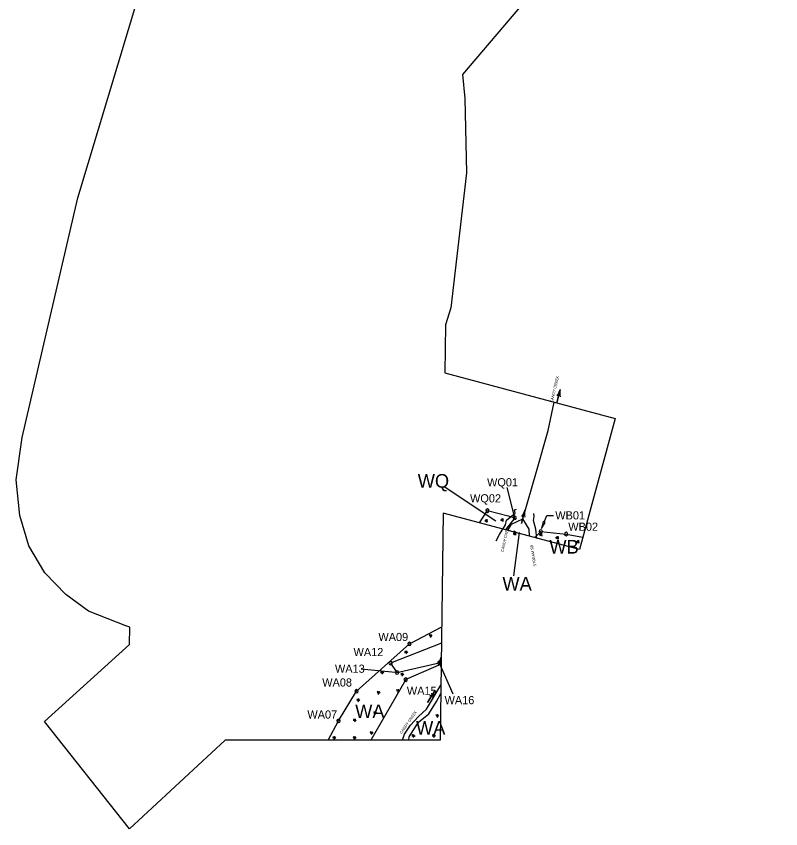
# Model space of a CAD drawing. Extents: x 1807340 to 1808565, y 913462 to 916154.
# Drawn here: x 1807340 to 1808463, y 913462 to 914655 of the extents above; entities that cross this region are included whole.
import ezdxf

# ---------------------------------------------------------------- set-up
doc = ezdxf.new("R2010")
doc.units = 0
for name, color, linetype in [('Default', 7, 'Continuous'), ('Exist Environmental Wetland Boundary', 7, 'Continuous'), ('Exist Hydro Jurisdictional Stream or Body of Water', 7, 'Continuous'), ('Exist Hydro River Flow Arrow CELL', 7, 'Continuous'), ('Exist Hydro Stream or Body of Water Text', 7, 'Continuous'), ('Old_Level_60', 7, 'Continuous'), ('Old_Level_61', 7, 'Continuous'), ('Prop PHM Study Limits Alternate 1', 7, 'Continuous')]:
    doc.layers.add(name, color=color, linetype=linetype)

# ---------------------------------------------------------------- blocks, each defined once
blk = doc.blocks.new('WetlandPoint')
at = {"layer": 'Default'}
for start, end in [(0, 180), (180, 0)]:
    blk.add_arc((0, 0), 0.782, start, end, dxfattribs=at)

msp = doc.modelspace()

# ---------------------------------------------------------------- linework, layer by layer
at = {"layer": 'Exist Environmental Wetland Boundary'}
for points in [[(1808020.3, 913911.2), (1808031.7, 913929.3), (1808062, 913921.8), (1808071.9, 913918.8), (1808058.3, 913901.1)], [(1808031.7, 913912.5), (1808031.6, 913914.6), (1808027.7, 913914.4), (1808031.6, 913914.6), (1808031.5, 913916.7)], [(1808055.1, 913913.6), (1808055, 913915.8), (1808051, 913915.5), (1808055, 913915.8), (1808054.9, 913917.9)], [(1808055.1, 913913.6), (1808055, 913915.8), (1808051, 913915.5), (1808055, 913915.8), (1808054.9, 913917.9)], [(1808074.5, 913896.8), (1808070.6, 913899.2), (1808070.5, 913897.9)], [(1808073.4, 913893.1), (1808073.3, 913895.3), (1808069.4, 913895.1), (1808073.3, 913895.3), (1808073.2, 913897.4)], [(1808101.2, 913889.7), (1808110, 913898.8), (1808147.3, 913895), (1808171.8, 913890.2)], [(1808112, 913892), (1808111.8, 913894.2), (1808107.9, 913894), (1808111.8, 913894.2), (1808111.7, 913896.3)], [(1808112, 913892), (1808111.8, 913894.2), (1808107.9, 913894), (1808111.8, 913894.2), (1808111.7, 913896.3)], [(1808136, 913887.5), (1808135.9, 913889.7), (1808131.9, 913889.4), (1808135.9, 913889.7), (1808135.8, 913891.8)], [(1808166.3, 913881.6), (1808166.2, 913883.8), (1808162.3, 913883.6), (1808166.2, 913883.8), (1808166.1, 913885.9)], [(1807797.7, 913592.3), (1807813, 913620.5), (1807839.6, 913664), (1807917.2, 913733.6), (1807964.6, 913758.5)], [(1807947.9, 913743.1), (1807949.3, 913744.7), (1807946.4, 913747.3), (1807949.3, 913744.7), (1807950.8, 913746.2)], [(1807964.3, 913734.5), (1807889.6, 913705.3), (1807898.9, 913691.6), (1807961, 913705.8), (1807964, 913714.1)], [(1807911.9, 913718.8), (1807913.3, 913720.3), (1807910.4, 913723), (1807913.3, 913720.3), (1807914.8, 913721.9)], [(1807963.9, 913704), (1807911.7, 913681.1), (1807860.6, 913592.3)], [(1807876.7, 913689), (1807878.1, 913690.6), (1807875.2, 913693.3), (1807878.1, 913690.6), (1807879.6, 913692.2)], [(1807906.2, 913686.1), (1807907.7, 913687.7), (1807904.8, 913690.4), (1807907.7, 913687.7), (1807909.1, 913689.3)], [(1807871.5, 913659.5), (1807872.9, 913661.1), (1807870, 913663.7), (1807872.9, 913661.1), (1807874.4, 913662.7)], [(1807899.9, 913662.3), (1807901.3, 913663.9), (1807898.4, 913666.6), (1807901.3, 913663.9), (1807902.8, 913665.5)], [(1807916.1, 913592.4), (1807916.8, 913596.9), (1807927.3, 913613.3), (1807930.7, 913618.6), (1807945.5, 913630.7), (1807956.8, 913649), (1807963.3, 913660.7)], [(1807841.5, 913648.5), (1807843, 913650.1), (1807840.1, 913652.7), (1807843, 913650.1), (1807844.4, 913651.6)], [(1807866.3, 913630), (1807867.7, 913631.5), (1807864.8, 913634.2), (1807867.7, 913631.5), (1807869.2, 913633.1)], [(1807957.7, 913625.6), (1807959.1, 913627.2), (1807956.2, 913629.9), (1807959.1, 913627.2), (1807960.6, 913628.8)], [(1807957.7, 913625.6), (1807959.1, 913627.2), (1807956.2, 913629.9), (1807959.1, 913627.2), (1807960.6, 913628.8)], [(1807836.3, 913618.9), (1807837.8, 913620.5), (1807834.9, 913623.2), (1807837.8, 913620.5), (1807839.2, 913622.1)], [(1807861.1, 913600.4), (1807862.5, 913602), (1807859.6, 913604.7), (1807862.5, 913602), (1807864, 913603.6)], [(1807806.2, 913593), (1807807.7, 913594.6), (1807804.8, 913597.3), (1807807.7, 913594.6), (1807809.1, 913596.2)], [(1807836.2, 913593.1), (1807837.7, 913594.7), (1807834.8, 913597.3), (1807837.7, 913594.7), (1807839.1, 913596.3)], [(1807922.5, 913596), (1807923.9, 913597.6), (1807921, 913600.3), (1807923.9, 913597.6), (1807925.4, 913599.2)], [(1807922.5, 913596), (1807923.9, 913597.6), (1807921, 913600.3), (1807923.9, 913597.6), (1807925.4, 913599.2)], [(1807952.5, 913596.1), (1807953.9, 913597.7), (1807951, 913600.3), (1807953.9, 913597.7), (1807955.4, 913599.3)], [(1807952.5, 913596.1), (1807953.9, 913597.7), (1807951, 913600.3), (1807953.9, 913597.7), (1807955.4, 913599.3)]]:
    msp.add_lwpolyline(points, dxfattribs=at)
for centre, radius, start, end in [((1808032.9, 913919.2), 4.81, 215.2622, 254.757), ((1808032, 913911.5), 3.07, 97.2751, 160.6697), ((1808056.2, 913920.4), 4.81, 215.2622, 254.757), ((1808056.2, 913920.4), 4.81, 215.2622, 254.757), ((1808055.4, 913912.7), 3.07, 97.2751, 160.6697), ((1808055.4, 913912.7), 3.07, 97.2751, 160.6697), ((1808074.6, 913899.9), 4.81, 215.2622, 254.757), ((1808073.7, 913892.2), 3.07, 97.2751, 160.6697), ((1808113.1, 913898.8), 4.81, 215.2622, 254.757), ((1808113.1, 913898.8), 4.81, 215.2622, 254.757), ((1808112.2, 913891.1), 3.07, 97.2751, 160.6697), ((1808112.2, 913891.1), 3.07, 97.2751, 160.6697), ((1808137.1, 913894.3), 4.81, 215.2622, 254.757), ((1808136.3, 913886.6), 3.07, 97.2751, 160.6697), ((1808167.5, 913888.4), 4.81, 215.2622, 254.757), ((1808166.6, 913880.7), 3.07, 97.2751, 160.6697), ((1807947.4, 913742.2), 3.07, 51.7816, 115.1762), ((1807953.5, 913747), 4.81, 169.7687, 209.2634), ((1807911.4, 913717.9), 3.07, 51.7816, 115.1762), ((1807917.5, 913722.7), 4.81, 169.7687, 209.2634), ((1807876.2, 913688.2), 3.07, 51.7816, 115.1762), ((1807882.3, 913693), 4.81, 169.7687, 209.2634), ((1807905.8, 913685.3), 3.07, 51.7816, 115.1762), ((1807911.9, 913690.1), 4.81, 169.7687, 209.2634), ((1807871, 913658.7), 3.07, 51.7816, 115.1762), ((1807877.1, 913663.4), 4.81, 169.7687, 209.2634), ((1807899.4, 913661.5), 3.07, 51.7816, 115.1762), ((1807905.5, 913666.3), 4.81, 169.7687, 209.2634), ((1807841.1, 913647.6), 3.07, 51.7816, 115.1762), ((1807847.2, 913652.4), 4.81, 169.7687, 209.2634), ((1807865.8, 913629.1), 3.07, 51.7816, 115.1762), ((1807871.9, 913633.9), 4.81, 169.7687, 209.2634), ((1807957.2, 913624.8), 3.07, 51.7816, 115.1762), ((1807957.2, 913624.8), 3.07, 51.7816, 115.1762), ((1807963.3, 913629.6), 4.81, 169.7687, 209.2634), ((1807963.3, 913629.6), 4.81, 169.7687, 209.2634), ((1807835.9, 913618.1), 3.07, 51.7816, 115.1762), ((1807842, 913622.9), 4.81, 169.7687, 209.2634), ((1807860.6, 913599.6), 3.07, 51.7816, 115.1762), ((1807866.7, 913604.3), 4.81, 169.7687, 209.2634), ((1807928.1, 913599.9), 4.81, 169.7687, 209.2634), ((1807928.1, 913599.9), 4.81, 169.7687, 209.2634), ((1807958.1, 913600), 4.81, 169.7687, 209.2634), ((1807958.1, 913600), 4.81, 169.7687, 209.2634), ((1807805.8, 913592.2), 3.07, 51.7816, 115.1762), ((1807811.9, 913597), 4.81, 169.7687, 209.2634), ((1807835.8, 913592.3), 3.07, 51.7816, 115.1762), ((1807841.9, 913597), 4.81, 169.7687, 209.2634), ((1807922, 913595.2), 3.07, 51.7816, 115.1762), ((1807922, 913595.2), 3.07, 51.7816, 115.1762), ((1807952, 913595.2), 3.07, 51.7816, 115.1762), ((1807952, 913595.2), 3.07, 51.7816, 115.1762)]:
    msp.add_arc(centre, radius, start, end, dxfattribs=at)
at = {"layer": 'Exist Hydro Jurisdictional Stream or Body of Water'}
for points in [[(1808044.4, 913885), (1808049.6, 913894.2), (1808058.4, 913908.5), (1808059.6, 913915.4), (1808072.7, 913925.8), (1808071.7, 913930.3), (1808074.2, 913931.6)], [(1808104.3, 913888.5), (1808102.9, 913902.2), (1808099.5, 913914.9), (1808100.6, 913920.8), (1808100.1, 913925.3)]]:
    msp.add_lwpolyline(points, dxfattribs=at)
at = {"layer": 'Exist Hydro River Flow Arrow CELL'}
for p, q in [((1808136.2, 914097.3), (1808136.2, 914097.3)), ((1808084.3, 913920.2), (1808084.3, 913920.2)), ((1807949.2, 913656.1), (1807949.2, 913656.1))]:
    msp.add_line(p, q, dxfattribs=at)
for points in [[(1808134, 914097.8), (1808135.2, 914099.5), (1808136.3, 914101.2), (1808137.2, 914103.1), (1808138, 914105), (1808138.6, 914107), (1808133.8, 914087.6), (1808138.6, 914107), (1808138.2, 914105), (1808138, 914102.9), (1808138, 914100.8), (1808138.1, 914098.7), (1808138.4, 914096.7)], [(1808082.1, 913920.8), (1808083.3, 913922.4), (1808084.4, 913924.2), (1808085.3, 913926), (1808086.1, 913928), (1808086.7, 913929.9), (1808081.9, 913910.5), (1808086.7, 913929.9), (1808086.3, 913927.9), (1808086.1, 913925.9), (1808086.1, 913923.8), (1808086.2, 913921.7), (1808086.5, 913919.7)], [(1807947.3, 913657.3), (1807949, 913658.5), (1807950.5, 913659.8), (1807952, 913661.3), (1807953.4, 913662.8), (1807954.5, 913664.5), (1807943.9, 913647.6), (1807954.5, 913664.5), (1807953.5, 913662.8), (1807952.7, 913660.9), (1807952, 913658.9), (1807951.5, 913656.9), (1807951.2, 913654.8)]]:
    msp.add_lwpolyline(points, dxfattribs=at)
at = {"layer": 'Old_Level_60'}
for p, q in [((1808044, 913914.1), (1807968.1, 913964.1)), ((1808071.9, 913918.8), (1808060.9, 913963.3)), ((1808078.6, 913897), (1808069.9, 913833.8)), ((1807896.4, 913691.6), (1807846.2, 913696.6)), ((1807961, 913705.8), (1807980.8, 913660.1))]:
    msp.add_line(p, q, dxfattribs=at)
for points in [[(1808093.3, 913891.8), (1808093, 913902.3), (1808083.7, 913917.2)], [(1808114.9, 913912.6), (1808118.9, 913922.4), (1808128.9, 913922.4)]]:
    msp.add_lwpolyline(points, dxfattribs=at)
msp.add_lwpolyline([(1808113.4, 913913.2), (1808111.2, 913903.3), (1808116.5, 913912)], close=True, dxfattribs=at)
at = {"layer": 'Old_Level_61'}
for points in [[(1808061.9, 913900.2), (1808067.1, 913909.7), (1808083.7, 913917.2), (1808103.8, 913986.7), (1808120.8, 914047.2), (1808130, 914088.7)], [(1808093.3, 913891.8), (1808093, 913902.3), (1808083.7, 913917.2)], [(1807907, 913592.4), (1807909.8, 913600.8), (1807918.7, 913614.2), (1807930.4, 913626.8), (1807942.1, 913637.6), (1807963.5, 913672.8)]]:
    msp.add_lwpolyline(points, dxfattribs=at)
at = {"layer": 'Prop PHM Study Limits Alternate 1'}
msp.add_lwpolyline([(1808462.5, 915119.6), (1807995.2, 914569.7), (1807998.7, 914534.4), (1808001.2, 914425.7), (1807978.2, 914227.3), (1807970.1, 914202.3), (1807969.2, 914131.7), (1808219.4, 914064.8), (1808166.9, 913872.2), (1807966.6, 913925.5), (1807962.5, 913592.4), (1807646.5, 913592.2), (1807506, 913462.1), (1807381.3, 913619.5), (1807506, 913732.8), (1807506.4, 913758.2), (1807500.7, 913760.3), (1807445.9, 913781.7), (1807412.6, 913806.1), (1807381.8, 913838.1), (1807358.4, 913877.8), (1807345.1, 913922), (1807339.7, 913974.5), (1807348.3, 914036.5), (1807430.1, 914388.9), (1807519.9, 914687)], dxfattribs=at)

# ---------------------------------------------------------------- block references
at = {"layer": 'Old_Level_60', "xscale": 3.198862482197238, "yscale": 3.198862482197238}
for p in [(1808031.7, 913929.3), (1808071.9, 913918.8), (1808110, 913898.8), (1808147.3, 913895), (1807917.2, 913733.6), (1807961, 913705.8), (1807889.6, 913705.3), (1807898.9, 913691.6), (1807911.7, 913681.1), (1807839.6, 913664), (1807813, 913620.5)]:
    msp.add_blockref('WetlandPoint', p, dxfattribs=at)

# ---------------------------------------------------------------- texts
at = {"layer": 'Exist Hydro Stream or Body of Water Text'}
for s, rotation, p in [('CANDY CREEK', 76.8624, (1808127.8, 914087.8)), ('CANDY CREEK', 76.8624, (1808055.3, 913868.4)), ('STREAM SB', 99.1249, (1808103.6, 913847.8)), ('CANDY CREEK', 55.2778, (1807905.8, 913601))]:
    msp.add_text(s, height=4, rotation=rotation, dxfattribs=at).set_placement(p)
at = {"layer": 'Old_Level_60'}
for s, height, p in [('WQ', 20, (1807929.4, 913963)), ('WQ01', 12, (1808031.2, 913965)), ('WQ02', 12, (1808006.2, 913941.4)), ('WB01', 12, (1808131.4, 913916.4)), ('WB02', 12, (1808150.5, 913899.7)), ('WB', 20, (1808122.7, 913866.3)), ('WA', 20, (1808053.8, 913812)), ('WA09', 12, (1807871.6, 913737.8)), ('WA12', 12, (1807835.1, 913715.6)), ('WA13', 12, (1807807.8, 913691.2)), ('WA08', 12, (1807789.1, 913671)), ('WA15', 12, (1807913.4, 913658.8)), ('WA16', 12, (1807968.8, 913645)), ('WA', 20, (1807837.5, 913624.6)), ('WA07', 12, (1807767.3, 913623.9)), ('WA', 20, (1807926.9, 913600.3))]:
    msp.add_text(s, height=height, dxfattribs=at).set_placement(p)

doc.saveas('drawing.dxf')
